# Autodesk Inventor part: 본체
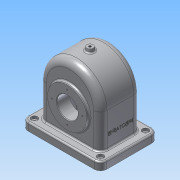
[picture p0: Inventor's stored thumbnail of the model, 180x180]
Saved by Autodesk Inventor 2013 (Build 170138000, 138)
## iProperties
Created: 2016-10
Part Number: 본체
Material: 알루미늄 6061
Document SubType Name: Modeling
Designer: Administrator
Density: 2.71 g/cm^3
Mass: 1165.05 g
Surface Area: 1200.06 cm^2
Volume: 429.908 cm^3
Author: Administrator
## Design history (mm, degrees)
sketch "스케치1"
  geometry: L1 (-58, 0)-(58, 0); L2 (-58, 0)-(-58, 80); L3 (58, 0)-(58, 80); L4 (0, 0)-(0, 144); A1 r 58 centre (0, 80) between (58, 80) and (-58, 80); 1 further point
  constraints: 8 end point, 2 parallel, 2 point on circle, 1 centre point, 1 coincident, 1 horizontal, 1 midpoint, 1 perpendicular, 1 tangent, 1 vertical alignment
  dimensions: "d12" = 116 diameter of A1; "d13" = 80 distance of point (0, 0) A1.centre
extrude "돌출1" new body sketch "스케치1" stored distance "d15" = 77; taper "d16" = 0 deg
sketch "스케치3"
  geometry: L1 (58, 80)-(58, 0) reference; L2 (58, 0)-(-58, 0) reference; L3 (58, 0)-(-58, 0) reference; L4 (-58, 0)-(-58, 80) reference; L5 (58, 80)-(58, 0) reference; L6 (52, 80)-(52, 0); L7 (-52, 80)-(-52, 0); A1 r 58 centre (0, 80) between (58, 80) and (-58, 80) reference; A2 r 58 centre (0, 80) between (58, 80) and (-58, 80) reference; A3 r 52 centre (0, 80) between (52, 80) and (-52, 80); 1 further point
  constraints: 4 end point, 2 parallel, 2 point on circle, 2 point on line, 2 tangent, 1 centre point
  dimensions: "d17" = 6 radial gap between concentric circles of A1 A3
extrude "돌출2" cut sketch "스케치3" stored distance "d19" = 67; taper "d20" = 0 deg
sketch "스케치5"
  geometry: L1 (-58, 0)-(58, 0) reference; C1 r 37.5 at (0, 65); A1 r 58 centre (0, 80) between (58, 80) and (-58, 80) reference; 1 further point
  constraints: 1 centre point, 1 vertical alignment
  dimensions: "d23" = 75 diameter of C1; "d25" = 65 distance from line of L1 C1.centre
extrude "돌출3" join sketch "스케치5" distance "d26" = 5; taper "d27" = 0 deg
node "작업 평면1"
sketch "스케치6"
  geometry: L1 (52, -65)-(-52, -65) reference; C1 r 28 at (0, 0); 2 further points
  constraints: 1 centre point, 1 midpoint, 1 vertical alignment
  dimensions: "d29" = 65 distance from line of L1 C1.centre; "d30" = 56 diameter of C1
extrude "돌출4" join sketch "스케치6" stored distance "d31" = 5; taper "d32" = 40 deg
sketch "스케치7"
  geometry: C1 r 37.5 at (0, 0) reference; C2 r 20 at (0, 0); 1 further point
  constraints: 1 centre point, 1 coincident
  dimensions: "d33" = 40 diameter of C2
extrude "돌출5" cut sketch "스케치7" distance "d34" = 24; taper "d35" = 0 deg
sketch "스케치8"
  geometry: L1 (58, 0)-(-58, 0) reference; C1 r 31 at (0, -65); 2 further points
  constraints: 1 centre point, 1 midpoint, 1 vertical alignment
  dimensions: "d36" = 62 diameter of C1; "d37" = 65 distance from line of L1 C1.centre
extrude "돌출6" join sketch "스케치8" distance "d38" = 10; taper "d39" = 0 deg
sketch "스케치9"
  geometry: C1 r 31 at (0, 0) reference; C2 r 20 at (0, 0); 1 further point
  constraints: 1 centre point, 1 coincident
  dimensions: "d40" = 40 diameter of C2
extrude "돌출7" cut sketch "스케치9" distance "d41" = 15; taper "d42" = 0 deg
sketch "스케치10"
  geometry: L1 (0, 0)-(0, -26); C1 r 31 at (0, 0) reference; 2 further points
  constraints: 2 end point, 1 coincident, 1 vertical
  dimensions: "d43" = 26 distance of L1.start L1.end
hole "구멍1" sketch "스케치10" at (0, -26) diameter "d44" = 2.459; stored, may be unused: countersink angle "d48" = 90 deg, drill point angle "d50" = 118 deg; dims "d45" = 6, "d46" = 4, "d47" = 2, "d49" = 8
chamfer "모따기1" distance "d54" = 1; stored, may be unused: second distance "d55" = 2, angle "d56" = 45 deg
node "작업 평면3"
sketch "스케치12"
  geometry: L1 (-110, -72)-(-6, -72) reference; C1 r 6 at (-58, -38.5); 1 further point
  constraints: 1 centre point, 1 coincident
  dimensions: "d63" = 12 diameter of C1; "d64" = 33.5 distance from line of C1.centre L1
extrude "돌출8" join sketch "스케치12" stored distance "d65" = 15; taper "d66" = 10 deg
fillet "모깎기3" dims "d67" = 3
fillet "모깎기1" dims "d57" = 8
fillet "모깎기2" dims "d58" = 13
hole "구멍2" diameter "d70" = 4.459; stored, may be unused: countersink angle "d74" = 90 deg, drill point angle "d76" = 118 deg; dims "d68" = 10, "d69" = 10, "d71" = 99, "d72" = 4, "d73" = 2, "d75" = 8
fillet "모깎기4" dims "d77" = 3
sketch "스케치13"
  geometry: L1 (0, 0)-(90, 0) reference; L2 (-13, -13)-(-13, -64) reference; L3 (90, -77)-(0, -77) reference; L4 (103, -64)-(103, -13) reference; L5 (120, -93.5)-(-30, -93.5); L6 (-30, -93.5)-(-30, 16.5); L7 (-30, 16.5)-(120, 16.5); L8 (120, 16.5)-(120, -93.5); L9 (120, -93.5)-(-30, 16.5); L10 (-30, -93.5)-(120, 16.5); A1 r 13 centre (90, -13) between (103, -13) and (90, 0) reference; A2 r 13 centre (0, -13) between (0, 0) and (-13, -13) reference; A3 r 13 centre (0, -64) between (-13, -64) and (0, -77) reference; A4 r 13 centre (90, -64) between (90, -77) and (103, -64) reference; 1 further point
  constraints: 12 end point, 2 midpoint, 2 parallel, 1 horizontal, 1 perpendicular
  dimensions: "d78" = 110 distance between parallel lines of L5 L7; "d80" = 150 distance of L6.end L7.end
extrude "돌출9" join sketch "스케치13" distance "d81" = 15; taper "d82" = 0 deg
fillet "모깎기5" dims "d83" = 12
fillet "모깎기6" dims "d84" = 3
hole "구멍3" diameter "d87" = 5; stored, may be unused: countersink angle "d91" = 82 deg, drill point angle "d93" = 118 deg; dims "d85" = 10, "d86" = 10, "d88" = 99, "d89" = 12, "d90" = 5, "d92" = 8
fillet "모깎기7" dims "d94" = 3
sketch "스케치14"
  geometry: L1 (80, -17.5)-(80, 68.5) reference; L2 (0, -13)-(62, -13) reference; 2 further points
  constraints: 1 other
  dimensions: "d95" = 40 distance from line of L1 point (40, 25.5); "d96" = 38.5 distance from line of point (40, 25.5) L2
feature "엠보싱1" sketch "스케치14" dims "d17" = 6, "d97" = 0.5, "d98" = 0
sketch "스케치15"
  geometry: L1 (0, 0)-(0, 29); C1 r 21 at (0, 0) reference; 2 further points
  constraints: 2 end point, 1 coincident, 1 vertical
  dimensions: "d99" = 29 distance of L1.start L1.end
hole "구멍4" sketch "스케치15" at (0, 29) diameter "d100" = 2.459; stored, may be unused: countersink angle "d104" = 82 deg, drill point angle "d106" = 118 deg; dims "d101" = 6, "d102" = 12, "d103" = 5, "d105" = 8
node "솔리드1"
pattern_circular "원형 패턴1" dims angle "d52" = 360 deg
mirror "대칭2"
mirror "대칭3"
pattern_circular "원형 패턴2" dims angle "d108" = 360 deg
node "투영된 루프1"
other parameters: "d28" = -24, "d62" = -144
